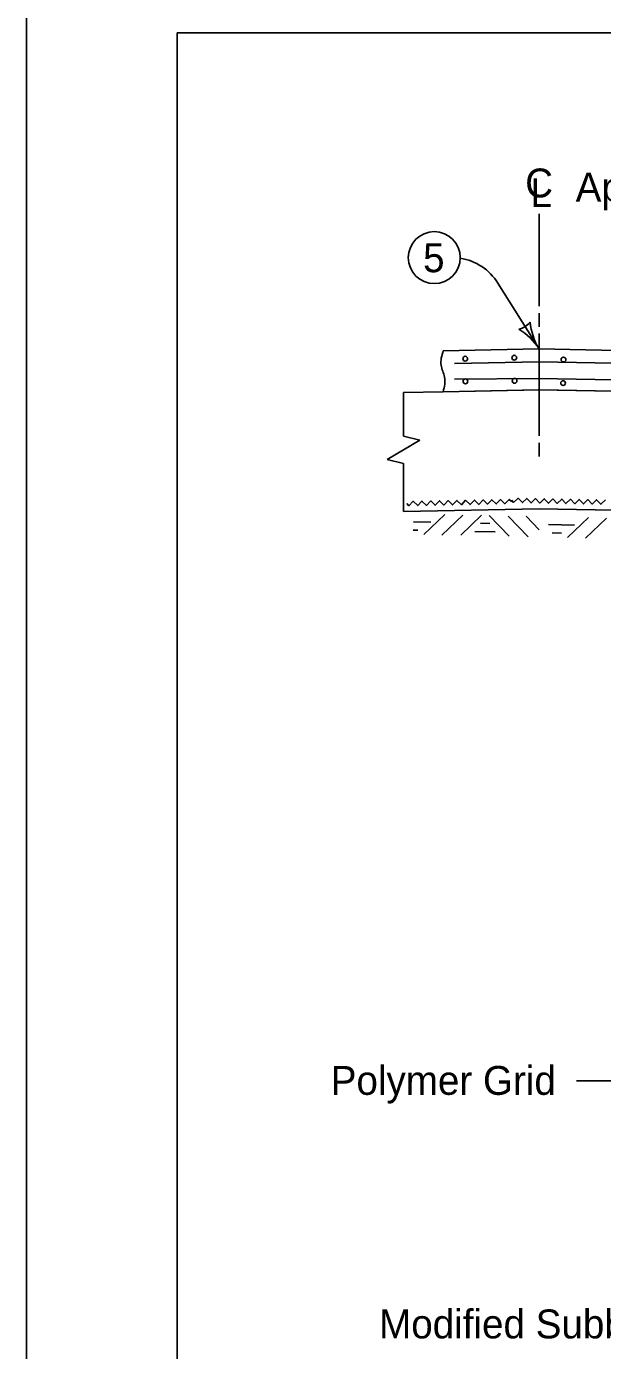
# Model space of a CAD drawing. Extents: x -2135039 to -2120895, y -2139150 to -2136566.
# Drawn here: x -2124239 to -2123840, y -2137949 to -2137032 of the extents above; entities that cross this region are included whole.
import ezdxf

# ---------------------------------------------------------------- set-up
doc = ezdxf.new("R2010")
doc.units = 0
for name, color, linetype in [('dsnDOTLogo', 7, 'Continuous'), ('Level 1', 7, 'Continuous'), ('Level 2', 7, 'Continuous'), ('Level 3', 7, 'Continuous')]:
    doc.layers.add(name, color=color, linetype=linetype)

msp = doc.modelspace()

# ---------------------------------------------------------------- linework, layer by layer
at = {"layer": 'dsnDOTLogo'}
msp.add_lwpolyline([(-2124238.96, -2139150.44), (-2120894.97, -2139150.44), (-2120894.97, -2136566.45), (-2124238.96, -2136566.45)], close=True, dxfattribs=at)
at = {"layer": 'Level 1'}
msp.add_lwpolyline([(-2124134.46, -2137035.95), (-2120999.47, -2137035.95), (-2120999.47, -2139045.94), (-2124134.46, -2139045.94)], close=True, dxfattribs=at)
at = {"layer": 'Level 2'}
for p, q in [((-2123912.29, -2137209.24), (-2123883.72, -2137254.79)), ((-2123883.73, -2137254.79), (-2123950.11, -2137256.13)), ((-2123883.73, -2137254.79), (-2123950.11, -2137256.13)), ((-2123173.47, -2137269.05), (-2123883.73, -2137254.79)), ((-2123883.73, -2137254.79), (-2123173.47, -2137269.05)), ((-2123883.73, -2137263.74), (-2123942.28, -2137264.86)), ((-2123883.73, -2137263.74), (-2123152.03, -2137278.43)), ((-2123883.77, -2137275.34), (-2123942.29, -2137275.74)), ((-2123950.11, -2137284.49), (-2123977.67, -2137285.04)), ((-2123977.67, -2137285.04), (-2123977.67, -2137315.3)), ((-2123883.16, -2137283.15), (-2123950.11, -2137284.49)), ((-2123950.11, -2137284.49), (-2123884.3, -2137283.17)), ((-2123884.3, -2137283.15), (-2123883.73, -2137283.16)), ((-2123884.3, -2137283.15), (-2123135.19, -2137298.18)), ((-2123883.73, -2137283.16), (-2123883.16, -2137283.15)), ((-2123883.16, -2137283.17), (-2123135.19, -2137298.18)), ((-2123977.67, -2137315.3), (-2123966.32, -2137318.14)), ((-2123977.67, -2137324.75), (-2123989.01, -2137331.37)), ((-2123966.32, -2137318.14), (-2123977.67, -2137324.75)), ((-2123989.01, -2137331.37), (-2123977.67, -2137334.21)), ((-2123977.67, -2137334.21), (-2123977.67, -2137367.47)), ((-2123883.73, -2137365.58), (-2123977.67, -2137367.47)), ((-2123949.04, -2137369.53), (-2123963.46, -2137383.38)), ((-2123936.6, -2137370), (-2123951.02, -2137383.86)), ((-2123923.59, -2137370.04), (-2123938.01, -2137383.89)), ((-2123918.18, -2137370.15), (-2123904.32, -2137384.57)), ((-2123905.18, -2137370.63), (-2123891.32, -2137385.06)), ((-2123892.72, -2137370.66), (-2123883.62, -2137380.13)), ((-2123883.73, -2137365.58), (-2123067.14, -2137381.97)), ((-2123849.51, -2137371.53), (-2123863.93, -2137385.38)), ((-2123837.07, -2137372), (-2123851.49, -2137385.86)), ((-2123857.66, -2137761.72), (-2123748.87, -2137761.72))]:
    msp.add_line(p, q, dxfattribs=at)
for points in [[(-2123883.73, -2137161.37), (-2123883.73, -2137225.33)], [(-2123883.72, -2137230.06), (-2123883.72, -2137239.52)], [(-2123883.73, -2137244.24), (-2123883.73, -2137315.14)], [(-2123884.3, -2137283.17), (-2123884.3, -2137283.15)], [(-2123883.16, -2137283.15), (-2123883.16, -2137283.17)], [(-2123883.73, -2137319.86), (-2123883.73, -2137329.32)], [(-2123975.4, -2137361.99), (-2123973.86, -2137363.47), (-2123970.89, -2137360.38), (-2123967.81, -2137363.35), (-2123964.85, -2137360.26), (-2123961.76, -2137363.22), (-2123958.8, -2137360.14), (-2123955.72, -2137363.1), (-2123952.75, -2137360.02), (-2123949.67, -2137362.98), (-2123946.7, -2137359.9), (-2123943.61, -2137362.86), (-2123940.65, -2137359.78), (-2123937.57, -2137362.74), (-2123934.61, -2137359.65), (-2123931.52, -2137362.62), (-2123928.56, -2137359.53), (-2123925.47, -2137362.5), (-2123922.5, -2137359.41), (-2123919.42, -2137362.37), (-2123916.46, -2137359.29), (-2123913.37, -2137362.25), (-2123910.41, -2137359.17), (-2123907.32, -2137362.13), (-2123904.36, -2137359.05), (-2123902.81, -2137360.53)], [(-2123902.81, -2137359.67), (-2123901.34, -2137361.21), (-2123898.25, -2137358.25), (-2123895.28, -2137361.34), (-2123892.2, -2137358.38), (-2123889.24, -2137361.46), (-2123886.15, -2137358.5), (-2123883.19, -2137361.58), (-2123880.11, -2137358.61), (-2123877.14, -2137361.7), (-2123874.06, -2137358.74), (-2123871.09, -2137361.82), (-2123868, -2137358.86), (-2123865.04, -2137361.95), (-2123861.96, -2137358.98), (-2123859, -2137362.07), (-2123855.91, -2137359.1), (-2123852.95, -2137362.18), (-2123849.86, -2137359.22), (-2123846.89, -2137362.31), (-2123843.81, -2137359.35), (-2123840.85, -2137362.43), (-2123837.76, -2137359.47)], [(-2123970.88, -2137380.37), (-2123967.61, -2137380.43)], [(-2123970.76, -2137374.57), (-2123958.73, -2137374.81)], [(-2123924.26, -2137375.52), (-2123917.73, -2137375.66)], [(-2123877.26, -2137376.44), (-2123859.2, -2137376.81)], [(-2123928.21, -2137381.3), (-2123914.02, -2137381.59)], [(-2123874.61, -2137382.3), (-2123868.08, -2137382.43)]]:
    msp.add_lwpolyline(points, dxfattribs=at)
for centre, radius in [((-2123956.32, -2137191.64), 18), ((-2123934.89, -2137261.63), 1.65), ((-2123900.86, -2137260.93), 1.65), ((-2123866.75, -2137262.22), 1.65), ((-2123934.74, -2137277.31), 1.65), ((-2123900.7, -2137276.95), 1.65), ((-2123867.02, -2137278.54), 1.65)]:
    msp.add_circle(centre, radius, dxfattribs=at)
for centre, radius, start, end in [((-2123944.32, -2137229.33), 37.81, 32.09002, 80.87761), ((-2123901.62, -2137226.25), 15.52, 284.35693, 319.82363), ((-2123901.62, -2137226.25), 15.52, 284.35693, 319.82363), ((-2123917.76, -2137276.14), 40.18, 32.09028, 60.16277), ((-2123917.76, -2137276.14), 40.18, 32.09028, 60.16277), ((-2123849.69, -2137233.45), 40.18, 184.01779, 212.09028), ((-2123849.69, -2137233.45), 40.18, 184.01779, 212.09028)]:
    msp.add_arc(centre, radius, start, end, dxfattribs=at)
msp.add_spline([(-2123950.11, -2137256.13), (-2123951.62, -2137266.21), (-2123949.16, -2137274.34), (-2123950.11, -2137284.49)], degree=3, dxfattribs=at)
msp.add_spline([(-2123950.11, -2137256.13), (-2123951.62, -2137266.21), (-2123949.16, -2137274.34), (-2123950.11, -2137284.49)], degree=3, dxfattribs=at)
at = {"layer": 'Level 3'}
msp.add_line((-2123152.22, -2137288.89), (-2123883.77, -2137275.34), dxfattribs=at)

# ---------------------------------------------------------------- texts
for s, p in [('C', (-2123893.33, -2137149.94)), ('Approach Roadway', (-2123858.32, -2137152.8)), ('L', (-2123889.73, -2137156.64)), ('5', (-2123964.08, -2137201.75)), ('Polymer Grid', (-2124028.1, -2137771.47)), ('Modified Subbase', (-2123994.56, -2137940.13))]:
    msp.add_text(s, height=20, dxfattribs=at).set_placement(p)

doc.saveas('drawing.dxf')
